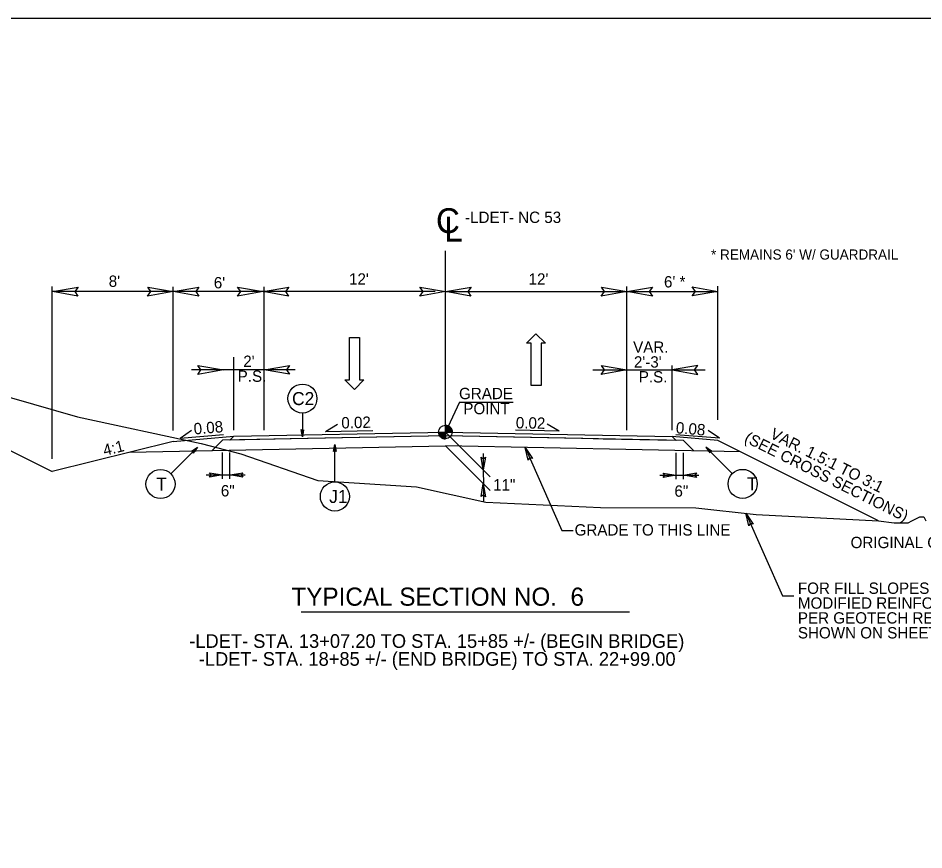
# Model space of a CAD drawing. Extents: x 1548135 to 1549339, y 868664 to 869085.
# Drawn here: x 1548186.8 to 1548246.7, y 868719.3 to 868774.3 of the extents above; entities that cross this region are included whole.
import ezdxf

# ---------------------------------------------------------------- set-up
doc = ezdxf.new("R2010")
doc.units = 0
for name, color, linetype in [('Default', 7, 'Continuous'), ('P_RDY_TC_Pvmt_Asphalt_Base_Course', 7, 'Continuous'), ('Prop Dimension', 7, 'Continuous'), ('Prop Terminator CELL', 7, 'Continuous'), ('Sheet_Data_Field_CELL', 7, 'Continuous'), ('Sheet_Plan', 7, 'Continuous'), ('Sheet_Title_Block_Text', 7, 'Continuous'), ('Typical Curb CELL', 7, 'Continuous'), ('Typical Grade Point Symbol CELL', 7, 'Continuous'), ('Typical Hinge Slope Arterial CELL', 7, 'Continuous'), ('Typical Hinge Slope Interstate CELL', 7, 'Continuous'), ('Typical Pavement Slope CELL', 7, 'Continuous'), ('Typical Pavement Slope Information CELL', 7, 'Continuous'), ('Typical Shoulder Slope CELL', 7, 'Continuous'), ('Typical Shoulder Slope Information CELL', 7, 'Continuous'), ('Typical Terminator CELL', 7, 'Continuous'), ('Typical Text Centerline CELL', 7, 'Continuous'), ('Typical Text General CELL', 7, 'Continuous'), ('Typical Text Grade Point CELL', 7, 'Continuous'), ('z - Construction', 7, 'Continuous')]:
    doc.layers.add(name, color=color, linetype=linetype)

msp = doc.modelspace()

# ---------------------------------------------------------------- linework, layer by layer
at = {"layer": 'Default'}
msp.add_lwpolyline([(1548135.05, 868774.324), (1548305.05, 868774.324), (1548305.05, 868664.324), (1548135.05, 868664.324)], close=True, dxfattribs=at)
at = {"layer": 'P_RDY_TC_Pvmt_Asphalt_Base_Course'}
for points in [[(1548190.739, 868755.947), (1548189.052, 868756.238), (1548190.749, 868756.538), (1548190.533, 868756.238)], [(1548195.362, 868756.528), (1548197.05, 868756.238), (1548195.353, 868755.938), (1548195.569, 868756.238)], [(1548198.737, 868755.947), (1548197.05, 868756.238), (1548198.747, 868756.538), (1548198.531, 868756.238)], [(1548201.303, 868756.528), (1548202.99, 868756.238), (1548201.294, 868755.938), (1548201.509, 868756.238)], [(1548204.678, 868755.947), (1548202.99, 868756.238), (1548204.687, 868756.538), (1548204.472, 868756.238)], [(1548213.362, 868756.528), (1548215.05, 868756.238), (1548213.353, 868755.938), (1548213.569, 868756.238)], [(1548216.737, 868755.947), (1548215.05, 868756.238), (1548216.747, 868756.538), (1548216.531, 868756.238)], [(1548225.362, 868756.528), (1548227.05, 868756.238), (1548225.353, 868755.938), (1548225.569, 868756.238)], [(1548228.737, 868755.947), (1548227.05, 868756.238), (1548228.747, 868756.538), (1548228.531, 868756.238)], [(1548231.374, 868756.546), (1548233.061, 868756.256), (1548231.364, 868755.956), (1548231.58, 868756.256)], [(1548198.675, 868751.355), (1548200.362, 868751.065), (1548198.665, 868750.765), (1548198.881, 868751.065)], [(1548204.737, 868750.774), (1548203.05, 868751.065), (1548204.747, 868751.365), (1548204.531, 868751.065)], [(1548225.362, 868751.355), (1548227.05, 868751.065), (1548225.353, 868750.765), (1548225.569, 868751.065)], [(1548231.737, 868751.355), (1548230.05, 868751.065), (1548231.747, 868750.765), (1548231.531, 868751.065)]]:
    msp.add_lwpolyline(points, close=True, dxfattribs=at)
at = {"layer": 'Prop Dimension'}
msp.add_line((1548243.699, 868741.081), (1548233.061, 868746.401), dxfattribs=at)
msp.add_lwpolyline([(1548243.699, 868741.081), (1548244.736, 868740.952), (1548244.996, 868740.952), (1548245.385, 868740.952), (1548245.644, 868740.952), (1548245.904, 868741.081), (1548246.163, 868741.212), (1548246.422, 868741.342), (1548246.682, 868741.342), (1548246.812, 868741.081)], dxfattribs=at)
at = {"layer": 'Prop Terminator CELL'}
msp.add_lwpolyline([(1548201.05, 868746.671), (1548215.05, 868746.951), (1548230.05, 868746.651), (1548230.3, 868746.396), (1548225.475, 868746.493), (1548224.141, 868746.52), (1548221.898, 868746.564), (1548215.05, 868746.701), (1548215.05, 868746.701), (1548204.78, 868746.496), (1548200.799, 868746.416)], close=True, dxfattribs=at)
at = {"layer": 'Sheet_Data_Field_CELL'}
for p in [(1548173.451, 868752.137), (1548197.05, 868746.338)]:
    msp.add_line(p, (1548189.05, 868744.338), dxfattribs=at)
at = {"layer": 'Sheet_Plan'}
for p, q in [((1548197.05, 868746.338), (1548201.05, 868746.671)), ((1548233.061, 868746.401), (1548230.05, 868746.651))]:
    msp.add_line(p, q, dxfattribs=at)
at = {"layer": 'Typical Curb CELL'}
for p, q in [((1548215.05, 868746.951), (1548215.05, 868747.399)), ((1548214.602, 868746.951), (1548215.05, 868746.951)), ((1548215.049, 868746.504), (1548215.05, 868746.951)), ((1548215.05, 868746.951), (1548215.049, 868746.504)), ((1548215.497, 868746.951), (1548215.05, 868746.951))]:
    msp.add_line(p, q, dxfattribs=at)
for points in [[(1548215.054, 868747.399), (1548215.054, 868747.399), (1548215.054, 868746.951)], [(1548215.063, 868747.399), (1548215.063, 868746.951)], [(1548215.072, 868747.398), (1548215.072, 868746.951)], [(1548215.081, 868747.398), (1548215.081, 868746.951)], [(1548215.09, 868747.397), (1548215.09, 868746.951)], [(1548215.099, 868747.396), (1548215.099, 868746.951)], [(1548215.108, 868747.395), (1548215.108, 868746.951)], [(1548215.117, 868747.394), (1548215.117, 868746.951)], [(1548215.125, 868747.393), (1548215.125, 868746.951)], [(1548215.134, 868747.391), (1548215.134, 868746.951)], [(1548215.143, 868747.389), (1548215.143, 868746.951)], [(1548215.152, 868747.387), (1548215.152, 868746.951)], [(1548215.161, 868747.385), (1548215.161, 868746.951)], [(1548215.17, 868747.382), (1548215.17, 868746.951)], [(1548215.179, 868747.38), (1548215.179, 868746.951)], [(1548215.188, 868747.377), (1548215.188, 868746.951)], [(1548215.197, 868747.374), (1548215.197, 868746.951)], [(1548214.604, 868746.951), (1548214.604, 868746.903)], [(1548214.613, 868746.951), (1548214.613, 868746.85)], [(1548214.622, 868746.951), (1548214.622, 868746.818)], [(1548214.631, 868746.951), (1548214.631, 868746.791)], [(1548214.64, 868746.951), (1548214.64, 868746.77)], [(1548214.649, 868746.951), (1548214.649, 868746.751)], [(1548214.658, 868746.951), (1548214.658, 868746.735)], [(1548214.667, 868746.951), (1548214.667, 868746.719)], [(1548214.676, 868746.951), (1548214.676, 868746.705)], [(1548214.685, 868746.951), (1548214.685, 868746.692)], [(1548214.694, 868746.951), (1548214.694, 868746.68)], [(1548214.703, 868746.951), (1548214.703, 868746.669)], [(1548214.712, 868746.951), (1548214.712, 868746.658)], [(1548214.721, 868746.951), (1548214.721, 868746.648)], [(1548214.73, 868746.951), (1548214.73, 868746.638)], [(1548214.739, 868746.951), (1548214.739, 868746.629)], [(1548214.747, 868746.951), (1548214.747, 868746.621)], [(1548214.756, 868746.951), (1548214.756, 868746.613)], [(1548214.765, 868746.951), (1548214.765, 868746.605)], [(1548214.774, 868746.951), (1548214.774, 868746.598)], [(1548214.783, 868746.951), (1548214.783, 868746.591)], [(1548214.792, 868746.951), (1548214.792, 868746.585)], [(1548214.801, 868746.951), (1548214.801, 868746.579)], [(1548214.81, 868746.951), (1548214.81, 868746.573)], [(1548214.819, 868746.951), (1548214.819, 868746.567)], [(1548214.828, 868746.951), (1548214.828, 868746.562)], [(1548214.837, 868746.951), (1548214.837, 868746.557)], [(1548214.846, 868746.951), (1548214.846, 868746.552)], [(1548214.855, 868746.951), (1548214.855, 868746.549)], [(1548214.864, 868746.951), (1548214.864, 868746.545)], [(1548214.873, 868746.951), (1548214.873, 868746.541)], [(1548214.882, 868746.951), (1548214.882, 868746.537)], [(1548214.891, 868746.951), (1548214.891, 868746.533)], [(1548214.9, 868746.951), (1548214.9, 868746.53)], [(1548214.909, 868746.951), (1548214.909, 868746.527)], [(1548214.918, 868746.951), (1548214.918, 868746.524)], [(1548214.927, 868746.951), (1548214.927, 868746.522)], [(1548214.935, 868746.951), (1548214.935, 868746.519)], [(1548214.944, 868746.951), (1548214.944, 868746.517)], [(1548214.953, 868746.951), (1548214.953, 868746.515)], [(1548214.962, 868746.951), (1548214.962, 868746.513)], [(1548214.971, 868746.951), (1548214.971, 868746.511)], [(1548214.98, 868746.951), (1548214.98, 868746.51)], [(1548214.989, 868746.951), (1548214.989, 868746.508)], [(1548214.998, 868746.951), (1548214.998, 868746.507)], [(1548215.007, 868746.951), (1548215.007, 868746.506)], [(1548215.016, 868746.951), (1548215.016, 868746.505)], [(1548215.025, 868746.951), (1548215.025, 868746.505)], [(1548215.034, 868746.951), (1548215.034, 868746.504)], [(1548215.043, 868746.951), (1548215.043, 868746.504), (1548215.043, 868746.504)], [(1548215.206, 868747.371), (1548215.206, 868746.951)], [(1548215.215, 868747.367), (1548215.215, 868746.951)], [(1548215.224, 868747.363), (1548215.224, 868746.951)], [(1548215.233, 868747.359), (1548215.233, 868746.951)], [(1548215.242, 868747.355), (1548215.242, 868746.951)], [(1548215.251, 868747.351), (1548215.251, 868746.951)], [(1548215.26, 868747.346), (1548215.26, 868746.951)], [(1548215.269, 868747.341), (1548215.269, 868746.951)], [(1548215.278, 868747.336), (1548215.278, 868746.951)], [(1548215.287, 868747.331), (1548215.287, 868746.951)], [(1548215.296, 868747.325), (1548215.296, 868746.951)], [(1548215.304, 868747.319), (1548215.304, 868746.951)], [(1548215.313, 868747.312), (1548215.313, 868746.951)], [(1548215.322, 868747.306), (1548215.322, 868746.951)], [(1548215.331, 868747.299), (1548215.331, 868746.951)], [(1548215.34, 868747.292), (1548215.34, 868746.951)], [(1548215.349, 868747.284), (1548215.349, 868746.951)], [(1548215.358, 868747.276), (1548215.358, 868746.951)], [(1548215.367, 868747.267), (1548215.367, 868746.951)], [(1548215.376, 868747.258), (1548215.376, 868746.951)], [(1548215.385, 868747.248), (1548215.385, 868746.951)], [(1548215.394, 868747.237), (1548215.394, 868746.951)], [(1548215.403, 868747.226), (1548215.403, 868746.951)], [(1548215.412, 868747.214), (1548215.412, 868746.951)], [(1548215.421, 868747.201), (1548215.421, 868746.951)], [(1548215.43, 868747.187), (1548215.43, 868746.951)], [(1548215.439, 868747.172), (1548215.439, 868746.951)], [(1548215.448, 868747.156), (1548215.448, 868746.951)], [(1548215.457, 868747.137), (1548215.457, 868746.951)], [(1548215.466, 868747.116), (1548215.466, 868746.951)], [(1548215.475, 868747.092), (1548215.475, 868746.951)], [(1548215.484, 868747.061), (1548215.484, 868746.951)], [(1548215.492, 868747.015), (1548215.492, 868746.951)]]:
    msp.add_lwpolyline(points, dxfattribs=at)
msp.add_circle((1548215.049, 868746.951), 0.448, dxfattribs=at)
for start, end in [(359.99048, 89.99048), (179.99048, 269.99048)]:
    msp.add_arc((1548215.049, 868746.951), 0.448, start, end, dxfattribs=at)
at = {"layer": 'Typical Grade Point Symbol CELL'}
for p, q in [((1548215.05, 868746.951), (1548215.05, 868758.944)), ((1548189.05, 868745.187), (1548189.05, 868756.583)), ((1548189.05, 868747.052), (1548189.05, 868756.563)), ((1548197.05, 868747.052), (1548197.05, 868756.563)), ((1548203.05, 868747.071), (1548203.05, 868756.563)), ((1548227.05, 868747.071), (1548227.05, 868756.583)), ((1548227.05, 868747.071), (1548227.05, 868756.583)), ((1548233.061, 868747.757), (1548233.061, 868756.601)), ((1548214.362, 868756.238), (1548189.05, 868756.238)), ((1548201.362, 868756.238), (1548199.362, 868756.238)), ((1548215.05, 868756.238), (1548233.061, 868756.238)), ((1548201.05, 868747.071), (1548201.05, 868751.915)), ((1548205.103, 868751.065), (1548198.255, 868751.065)), ((1548224.8, 868751.065), (1548232.23, 868751.065)), ((1548230.05, 868747.071), (1548230.05, 868751.361))]:
    msp.add_line(p, q, dxfattribs=at)
at = {"layer": 'Typical Hinge Slope Arterial CELL'}
msp.add_line((1548215.974, 868748.938), (1548219.531, 868748.938), dxfattribs=at)
at = {"layer": 'Typical Hinge Slope Interstate CELL'}
for p, q in [((1548205.59, 868748.205), (1548205.59, 868746.643)), ((1548218.001, 868744), (1548215.05, 868746.951)), ((1548199.05, 868746.505), (1548201.05, 868746.671)), ((1548201.05, 868746.671), (1548200.799, 868746.416)), ((1548230.801, 868746.386), (1548215.05, 868746.701)), ((1548194.165, 868745.617), (1548215.05, 868746.035)), ((1548196.887, 868744.197), (1548198.645, 868745.954)), ((1548200.3, 868743.86), (1548200.3, 868745.61)), ((1548200.8, 868743.86), (1548200.8, 868745.61)), ((1548207.738, 868743.655), (1548207.738, 868746.141)), ((1548234.574, 868745.644), (1548215.05, 868746.035)), ((1548218.001, 868743.083), (1548215.05, 868746.035)), ((1548230.301, 868743.84), (1548230.301, 868745.59)), ((1548230.801, 868743.84), (1548230.801, 868745.59)), ((1548234.024, 868744.206), (1548232.266, 868745.964)), ((1548217.555, 868745.525), (1548217.557, 868742.393)), ((1548199.222, 868744.115), (1548201.811, 868744.117)), ((1548229.222, 868744.095), (1548231.812, 868744.097))]:
    msp.add_line(p, q, dxfattribs=at)
for points in [[(1548173.451, 868752.137), (1548181.958, 868750.471), (1548190.725, 868747.96), (1548198.891, 868746.191), (1548201.527, 868745.504), (1548206.62, 868743.747), (1548213.126, 868743.34), (1548217.711, 868742.308), (1548225.305, 868741.975), (1548231.608, 868741.944), (1548235.593, 868741.508), (1548243.699, 868741.081)], [(1548220.317, 868745.929), (1548222.753, 868740.439), (1548223.504, 868740.439)], [(1548234.912, 868741.583), (1548237.336, 868736.118), (1548238.087, 868736.118)]]:
    msp.add_lwpolyline(points, dxfattribs=at)
for points in [[(1548205.671, 868747.111), (1548205.59, 868746.643), (1548205.507, 868747.114), (1548205.59, 868747.054)], [(1548198.256, 868745.68), (1548198.645, 868745.954), (1548198.37, 868745.562), (1548198.354, 868745.663)], [(1548207.657, 868745.672), (1548207.738, 868746.141), (1548207.821, 868745.67), (1548207.738, 868745.73)], [(1548220.526, 868745.099), (1548220.317, 868745.929), (1548220.798, 868745.215), (1548220.618, 868745.252)], [(1548232.655, 868745.689), (1548232.266, 868745.964), (1548232.541, 868745.572), (1548232.557, 868745.673)], [(1548217.7, 868745.29), (1548217.555, 868744.446), (1548217.405, 868745.295), (1548217.555, 868745.187)], [(1548199.456, 868744.261), (1548200.3, 868744.116), (1548199.452, 868743.966), (1548199.559, 868744.116)], [(1548201.644, 868743.971), (1548200.8, 868744.116), (1548201.648, 868744.266), (1548201.541, 868744.116)], [(1548229.457, 868744.241), (1548230.301, 868744.096), (1548229.452, 868743.946), (1548229.56, 868744.096)], [(1548231.645, 868743.951), (1548230.801, 868744.096), (1548231.649, 868744.246), (1548231.542, 868744.096)], [(1548217.411, 868742.685), (1548217.556, 868743.528), (1548217.706, 868742.68), (1548217.556, 868742.788)], [(1548235.121, 868740.753), (1548234.912, 868741.583), (1548235.393, 868740.868), (1548235.212, 868740.906)]]:
    msp.add_lwpolyline(points, close=True, dxfattribs=at)
for centre in [(1548205.59, 868749.166), (1548196.207, 868743.517), (1548234.704, 868743.526), (1548207.738, 868742.694)]:
    msp.add_circle(centre, 0.962, dxfattribs=at)
at = {"layer": 'Typical Pavement Slope CELL'}
msp.add_line((1548201.05, 868746.671), (1548215.05, 868746.951), dxfattribs=at)
at = {"layer": 'Typical Pavement Slope Information CELL'}
for p, q in [((1548207.124, 868746.993), (1548207.907, 868747.467)), ((1548222.571, 868747.009), (1548221.788, 868747.483)), ((1548197.497, 868746.554), (1548198.249, 868747.076)), ((1548197.497, 868746.554), (1548200.38, 868746.794)), ((1548207.124, 868746.993), (1548210.245, 868747.056)), ((1548222.571, 868747.009), (1548219.678, 868747.067)), ((1548233.172, 868746.54), (1548230.289, 868746.78)), ((1548233.172, 868746.54), (1548232.421, 868747.062))]:
    msp.add_line(p, q, dxfattribs=at)
at = {"layer": 'Typical Shoulder Slope CELL'}
msp.add_line((1548215.974, 868748.938), (1548215.05, 868746.951), dxfattribs=at)
at = {"layer": 'Typical Shoulder Slope Information CELL'}
for p, q in [((1548220.414, 868752.821), (1548221.034, 868753.451)), ((1548221.034, 868753.451), (1548221.674, 868752.821)), ((1548208.696, 868750.407), (1548208.696, 868753.207)), ((1548208.696, 868753.207), (1548209.356, 868753.207)), ((1548209.356, 868753.207), (1548209.356, 868750.407)), ((1548220.714, 868752.821), (1548220.414, 868752.821)), ((1548220.714, 868750.021), (1548220.714, 868752.821)), ((1548221.674, 868752.821), (1548221.374, 868752.821)), ((1548221.374, 868752.821), (1548221.374, 868750.021)), ((1548209.036, 868749.777), (1548208.396, 868750.407)), ((1548208.396, 868750.407), (1548208.696, 868750.407)), ((1548209.656, 868750.407), (1548209.036, 868749.777)), ((1548209.356, 868750.407), (1548209.656, 868750.407)), ((1548221.374, 868750.021), (1548220.714, 868750.021))]:
    msp.add_line(p, q, dxfattribs=at)
at = {"layer": 'Typical Terminator CELL'}
msp.add_line((1548205.498, 868735.067), (1548227.219, 868735.067), dxfattribs=at)
at = {"layer": 'Typical Text Grade Point CELL'}
for p, q in [((1548215.05, 868746.951), (1548230.05, 868746.651)), ((1548200.3, 868746.406), (1548199.632, 868745.726)), ((1548215.05, 868746.701), (1548200.3, 868746.406)), ((1548230.05, 868746.651), (1548230.3, 868746.396)), ((1548230.801, 868746.386), (1548231.468, 868745.706))]:
    msp.add_line(p, q, dxfattribs=at)

# ---------------------------------------------------------------- texts
at = {"layer": 'Sheet_Data_Field_CELL'}
for s, rotation, p in [('(SEE CROSS SECTIONS)', 333.43403, (1548234.759, 868746.334)), ('VAR. 1.5:1 TO 3:1', 333.43403, (1548236.459, 868746.583)), ('4:1', 14.03624, (1548192.507, 868745.368))]:
    msp.add_text(s, height=0.75, rotation=rotation, dxfattribs=at).set_placement(p)
msp.add_text('ORIGINAL GROUND', height=0.75, dxfattribs=at).set_placement((1548241.847, 868739.276))
at = {"layer": 'Sheet_Title_Block_Text'}
msp.add_text('C', height=1.64, dxfattribs=at).set_placement((1548214.423, 868760.112))
msp.add_text('L', height=1.641, rotation=359.9469, dxfattribs=at).set_placement((1548214.968, 868759.552))
at = {"layer": 'Typical Hinge Slope Arterial CELL'}
msp.add_text('  TYPICAL SECTION NO.  6', height=1.2, dxfattribs=at).set_placement((1548203.972, 868735.469))
at = {"layer": 'Typical Hinge Slope Interstate CELL'}
for s, height, p in [('-LDET- NC 53', 0.75, (1548216.35, 868760.779)), ('C2', 0.8608, (1548204.904, 868748.736)), ('T', 0.861, (1548195.924, 868743.086)), ('11"', 0.75, (1548218.202, 868743.088)), ('T', 0.861, (1548234.987, 868743.096)), ('6"', 0.75, (1548200.195, 868742.696)), ('6"', 0.75, (1548230.196, 868742.676)), ('J1', 0.8608, (1548207.359, 868742.264)), ('GRADE TO THIS LINE', 0.75, (1548223.592, 868740.109)), ('FOR FILL SLOPES 2:1 (OR STEEPER) USE', 0.75, (1548238.361, 868736.254)), ('MODIFIED REINFORCED SOIL SLOPE', 0.75, (1548238.361, 868735.271)), ('PER GEOTECH RECOMMENDATIONS', 0.75, (1548238.361, 868734.288)), ('SHOWN ON SHEET 2G-1', 0.75, (1548238.361, 868733.305))]:
    msp.add_text(s, height=height, dxfattribs=at).set_placement(p)
at = {"layer": 'Typical Pavement Slope Information CELL'}
for rotation, p in [(1.45507, (1548208.173, 868747.188)), (358.85436, (1548219.698, 868747.202))]:
    msp.add_text('0.02', height=0.75, rotation=rotation, dxfattribs=at).set_placement(p)
at = {"layer": 'Typical Shoulder Slope CELL'}
for s, p in [("8'", (1548192.78, 868756.554)), ("6'", (1548199.73, 868756.456)), ("12'", (1548208.673, 868756.699)), ("12'", (1548220.55, 868756.699)), ("6' *", (1548229.505, 868756.513)), ('GRADE', (1548215.948, 868749.127)), ('POINT', (1548216.233, 868748.133))]:
    msp.add_text(s, height=0.75, dxfattribs=at).set_placement(p)
at = {"layer": 'Typical Text Centerline CELL'}
for s, p in [('VAR. ', (1548227.463, 868752.197)), ("2'", (1548201.677, 868751.258)), ("2'-3'", (1548227.515, 868751.214)), ('P.S.', (1548201.308, 868750.275)), ('P.S.', (1548227.836, 868750.231))]:
    msp.add_text(s, height=0.75, dxfattribs=at).set_placement(p)
at = {"layer": 'Typical Text General CELL'}
for s, height, p in [("* REMAINS 6' W/ GUARDRAIL", 0.66824, (1548232.616, 868758.358)), ('-LDET- STA. 13+07.20 TO STA. 15+85 +/- (BEGIN BRIDGE)', 0.90387, (1548198.105, 868732.683)), ('-LDET- STA. 18+85 +/- (END BRIDGE) TO STA. 22+99.00 ', 0.90387, (1548198.735, 868731.498))]:
    msp.add_text(s, height=height, dxfattribs=at).set_placement(p)
at = {"layer": 'z - Construction'}
for rotation, p in [(4.76147, (1548198.43, 868746.788)), (355.23853, (1548230.264, 868746.878))]:
    msp.add_text('0.08', height=0.75, rotation=rotation, dxfattribs=at).set_placement(p)

doc.saveas('drawing.dxf')
